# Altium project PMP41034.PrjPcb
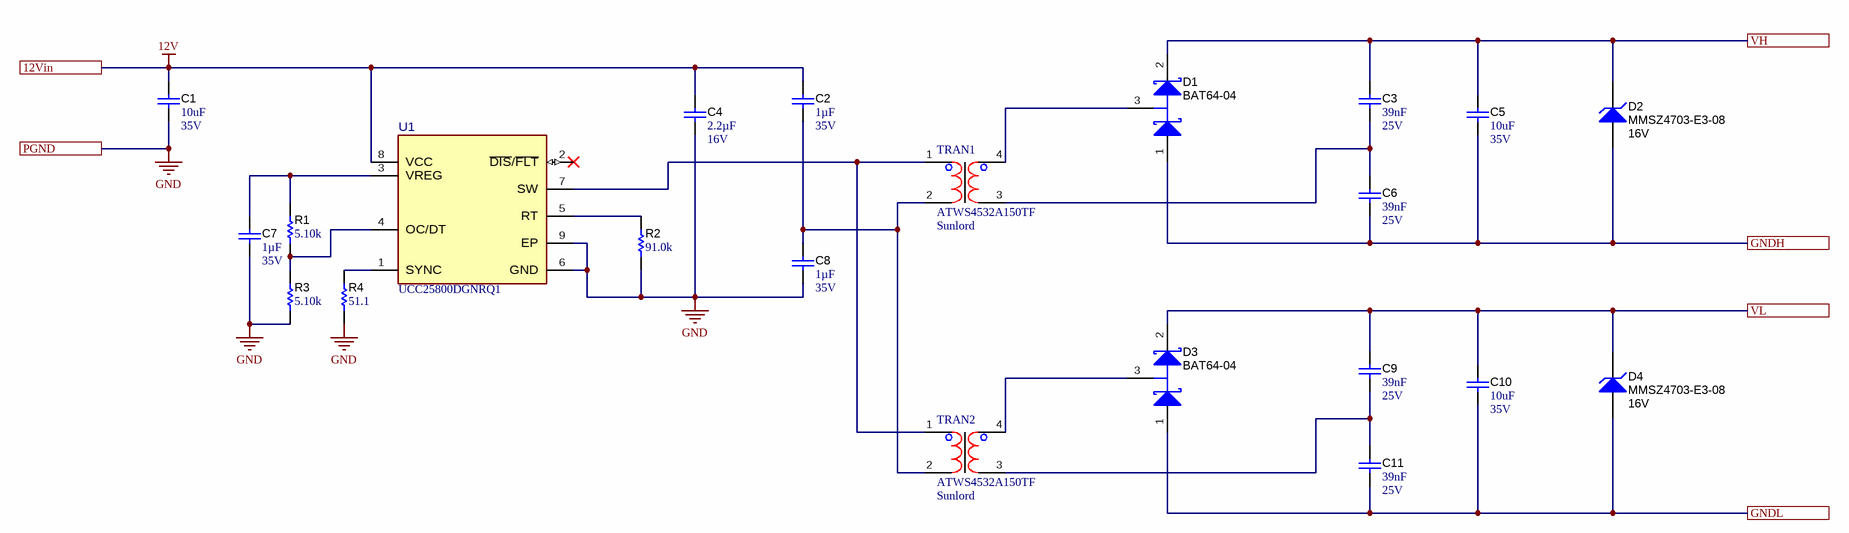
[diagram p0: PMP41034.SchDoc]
CopyrightYear: 2018; PCB_Layout: Who did the Layout?; PCB_Rev: E1; PRJ_Customer: Public Release; PRJ_Engineer: Enter name of project lead; PRJ_Number: XXX###; PRJ_Title: Change in menu Project|Project Options|Parameters; SCH_Rev: E1; TechSupport: http://www.ti.com/support; TID: N/A
1 sheet, 22 parts. Net scope: flat (ports and power ports of the same name join across sheets).
Board file: PMP41034.PcbDoc

## Sheet PMP41034.SchDoc
size 431 x 279 mm; Date: Not shown in title block; ApprovedBy: Not shown in title block; CheckedBy: Not shown in title block; Author: Not shown in title block; CompanyName: Not shown in title block; Engineer: Not shown in title block; Organization: Not shown in title block; Address1: Not shown in title block; Address2: Not shown in title block; Address3: Not shown in title block; Address4: Not shown in title block; DocumentNumber: 2; Revision: Use project parameter SCH_Rev; SheetNumber: 1; SheetTotal: 1; PageSetup: Record=PageOptions¦CenterHorizontal=True¦CenterVertical=True¦PrintScale=1.00¦XCorrection=1.00¦YCorrection=1.00¦PrintKind=0¦BorderSize=5000000¦LeftOffset=0¦BottomOffset=0¦Orientation=2¦PaperLength=1000¦PaperWidth=1000¦Scale=100¦PaperSource=15¦PrintQuality=600¦MediaType=1¦DitherType=10¦PaperKind=Letter¦PrintScaleMode=1

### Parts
C1  ValueDisplayed: 10uF  VDC_V: 35V  [0603]  (hidden comment: GRM188R6YA106MA73D)
C2  Cap_F: 1µF  VDC_V: 35V  [0603]  (hidden comment: GMK107AB7105KAHT)
C3  Cap_F: 39nF  VDC_V: 25V  [0603]  (hidden comment: 06033C393KAT2A)
C4  Cap_F: 2.2µF  VDC_V: 16V  [0603]  (hidden comment: EMK107BB7225MA-T)
C5  ValueDisplayed: 10uF  VDC_V: 35V  [0603]  (hidden comment: GRM188R6YA106MA73D)
C6  Cap_F: 39nF  VDC_V: 25V  [0603]  (hidden comment: 06033C393KAT2A)
C7  Cap_F: 1µF  VDC_V: 35V  [0603]  (hidden comment: GMK107AB7105KAHT)
C8  Cap_F: 1µF  VDC_V: 35V  [0603]  (hidden comment: GMK107AB7105KAHT)
C9  Cap_F: 39nF  VDC_V: 25V  [0603]  (hidden comment: 06033C393KAT2A)
C10  ValueDisplayed: 10uF  VDC_V: 35V  [0603]  (hidden comment: GRM188R6YA106MA73D)
C11  Cap_F: 39nF  VDC_V: 25V  [0603]  (hidden comment: 06033C393KAT2A)
D1  BAT64-04  [SOT-23]
D2  MMSZ4703-E3-08  value 16V  [SOD-123]
D3  BAT64-04  [SOT-23]
D4  MMSZ4703-E3-08  value 16V  [SOD-123]
R1  ValueDisplayed: 5.10k  [0603]  (hidden comment: RC0603FR-075K1L)
R2  ValueDisplayed: 91.0k  [0603]  (hidden comment: RC0603FR-0791KL)
R3  ValueDisplayed: 5.10k  [0603]  (hidden comment: RC0603FR-075K1L)
R4  ValueDisplayed: 51.1  [0603]  (hidden comment: CRCW060351R1FKEA)
TRAN1  Manufacturer: Sunlord  [SL4532]  (hidden comment: ATWS4532A150TF)
TRAN2  Manufacturer: Sunlord  [SL4532]  (hidden comment: ATWS4532A150TF)
U1  UCC25800DGNRQ1  [DGN0008G-MFG]

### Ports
12Vin, GNDH, GNDL, PGND, VH, VL

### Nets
12V: C1.1 C2.1 C4.1 U1.8(VCC) ; port 12Vin
GND: C1.2 C4.2 C7.2 C8.2 R2.1 R3.1 R4.1 U1.6(GND) U1.9(EP) ; port PGND
GNDH: C5.2 C6.2 D1.1(A) D2.2(A) ; port GNDH
GNDL: C10.2 C11.2 D3.1(A) D4.2(A) ; port GNDL
VH: C3.1 C5.1 D1.2(K) D2.1(K) ; port VH
VL: C9.1 C10.1 D3.2(K) D4.1(K) ; port VL
NetC2_2: C2.2 C8.1 TRAN1.2 TRAN2.2
NetC3_2: C3.2 C6.1 TRAN1.3
NetC7_1: C7.1 R1.2 U1.3(VREG)
NetC9_2: C9.2 C11.1 TRAN2.3
NetD1_3: D1.3(C) TRAN1.4
NetD3_3: D3.3(C) TRAN2.4
NetR1_1: R1.1 R3.2 U1.4(OC/DT)
NetR2_2: R2.2 U1.5(RT)
NetR4_2: R4.2 U1.1(SYNC)
NetTRAN1_1: TRAN1.1 TRAN2.1 U1.7(SW)

Not connected (* = marked no-connect by the designer): U1 2(~{DIS}/~{FLT})*

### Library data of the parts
C1 C5 C10 = CMP-0007355-6: CAP, CERM, 10 uF, 35 V, +/- 20%, X5R, 0603; Manufacturer: Murata; TaMax_C: 85°C; Value1: Unknown; TaMin_C: -55°C; Value: 10uF; SizeZ_mm: 1; SizeArea_mm2: 1.28; AEC Category: Q200; Cap_F: 10µF; SizeY_mm: 0.8; AEC Qualified: N; SizeX_mm: 1.6; SizeAreaWB_mm2: 4.68; U/M: EA
C2 C7 C8 = CMP-0007149-4: CAP, CERM, 1 uF, 35 V, +/- 10%, X7R, AEC-Q200 Grade 0, 0603; Manufacturer: Taiyo Yuden; TaMin_C: -55°C; Polarized: N; SizeAreaWB_mm2: 4.68; Value1: Unknown; U/M: EA; Value: 1uF; TaMax_C: 125°C; SizeZ_mm: 1; SizeX_mm: 1.6; SizeY_mm: 0.8; SizeArea_mm2: 1.28; AEC Qualified: Y; AEC Grade: 0; AEC Category: Q200
C3 C6 C9 C11 = CMP-0006756-4: CAP, CERM, 0.039 uF, 25 V, +/- 10%, X7R, 0603; Manufacturer: AVX; TaMin_C: -55°C; Polarized: N; SizeAreaWB_mm2: 4.68; Value1: 0.056 ohm; U/M: EA; TaMax_C: 125°C; SizeZ_mm: 1; SizeX_mm: 1.6; SizeY_mm: 0.8; SizeArea_mm2: 1.28; AEC Category: Q200; ESR_ohm: 56m
C4 = CMP-0064934-4: CAP, CERM, 2.2 uF, 16 V,+/- 10%, X7R, 0603; Manufacturer: Taiyo Yuden; TaMin_C: -55°C; Polarized: N; SizeAreaWB_mm2: 4.68; Value1: Unknown; U/M: EA; Value: 2.2uF; TaMax_C: 125°C; SizeZ_mm: 1; SizeX_mm: 1.6; SizeY_mm: 0.8; SizeArea_mm2: 1.28; AEC Category: Q200
D1 D3 = CMP-0028456-1: Diode, Schottky, 30 V, 0.2 A, SOT-23; Manufacturer: Diodes Inc.; Io_A: 200mA; Green_Lifecycle: Active; SizeAreaWB_mm2: 14; Vr_V: 30V; Green_REACh: Passed; Value1: 0.2A; TJmax_C: 125°C; U/M: EA; Value: 30V; SizeZ_mm: 1.1; SizeX_mm: 2.5; SizeY_mm: 3; Vf_V: 650mV; Value2: 0.65V; SizeArea_mm2: 7.5; AEC Category: Q101
D2 D4 = CMP-0077613-3: Diode, Zener, 16 V, 500 mW, SOD-123; Manufacturer: Vishay-Semiconductor; Power_W: 500mW; SizeZ_mm: 1.35; SizeY_mm: 1.7; SizeX_mm: 3.85; SizeArea_mm2: 6.545; SizeAreaWB_mm2: 13.095; Value1: 0.5W; AEC Qualified: N; RJA_CperW: 340; AEC Category: Q101
R1 R3 = CMP-0023198-5: RES, 5.10 k, 1%, 0.1 W, 0603; Manufacturer: Yageo; Power_W: 100mW; TempCo: 100 ppm/C; Value_Code: 5k10; Value: 5.10k; Res_ohm: 5.1k; SizeX_mm: 1.6; SizeY_mm: 0.8; SizeZ_mm: 1; Value2: 0.1W; SizeArea_mm2: 1.28; AEC Qualified: N; AEC Category: Q200; VDC_V: 75V; SizeAreaWB_mm2: 4.68
R2 = CMP-0023318-5: RES, 91.0 k, 1%, 0.1 W, 0603; Manufacturer: Yageo; Power_W: 100mW; TempCo: 100 ppm/C; Value_Code: 91k0; Value: 91.0k; Res_ohm: 91k; SizeX_mm: 1.6; SizeY_mm: 0.8; SizeZ_mm: 1; Value2: 0.1W; SizeArea_mm2: 1.28; AEC Qualified: N; VDC_V: 75V; AEC Category: Q200; SizeAreaWB_mm2: 4.68
R4 = CMP-0022483-4: RES, 51.1, 1%, 0.1 W, AEC-Q200 Grade 0, 0603; Manufacturer: Vishay-Dale; Power_W: 100mW; TempCo: 100 ppm/C; Value_Code: 51R1; Value: 51.1; EIA_Code: E96; SizeX_mm: 1.6; SizeY_mm: 0.8; SizeZ_mm: 1; Value2: 0.1W; SizeArea_mm2: 1.28; AEC Qualified: Y; VDC_V: 75V; AEC Category: Q200; AEC Grade: 0
TRAN1 TRAN2 = SL4532: Tranformer 4.5mm x 3.2mm, 3.45mm height; Value: 18:18
U1 = CMP-0088494-2: Open Loop LLC Transformer Driver for Isolated Bias Supplies; Manufacturer: Texas Instruments; Min Supply Voltage: 12V; SizeZ_mm: 1.1mm; Number Of Outputs: 1; Standoff Height: 0.05mm; AEC Category: Q200; Max Duty Cycle: 50%; TaMin_C: -40°C; TJmax_C: +150°C; AEC Qualified: No; Switching Frequency: 100-2000kHz; CompType: IC; Max Supply Voltage: 36V; TaMax_C: +125°C; Output Type: Other; Nominal Supply Current: 500uA

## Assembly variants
001: not fitted FID1 FID2 FID3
